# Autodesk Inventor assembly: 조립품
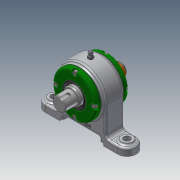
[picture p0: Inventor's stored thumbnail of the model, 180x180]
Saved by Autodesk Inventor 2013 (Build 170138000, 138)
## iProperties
Created: 2019-05
Part Number: 조립품
Document SubType Name: Assembly
Designer: user
Author: user
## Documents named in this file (14)
- C:\Users\user\Desktop\490504V1023\조립품.iam
- C:\Users\user\Desktop\490504V1023\본체.ipt
- C:\Users\user\Desktop\490504V1023\개스킷.ipt
- C:\Users\user\Desktop\490504V1023\그리스니플 M6.ipt
- 그리스니플  M6.ipt
- C:\Users\user\Desktop\490504V1023\그리스니플개스킷.ipt
- C:\Users\user\Desktop\490504V1023\볼트 M4.ipt
- C:\Users\user\Desktop\490504V1023\앵귤러 볼 베어링 7205.ipt
- C:\Users\user\Desktop\490504V1023\오일 실 28 40 5 B.ipt
- C:\Users\user\Desktop\490504V1023\커버.ipt
- C:\Users\user\Desktop\490504V1023\베어링너트_MIR.ipt
- C:\Users\user\Desktop\490504V1023\축_MIR.ipt
- C:\Users\user\Desktop\490504V1023\칼라_MIR.ipt
- C:\Users\user\Desktop\490504V1023\커버_MIR.ipt
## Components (4 placed, 3 different names)
1. 개스킷:1
2. 그리스니플  M6:1
3. 그리스니플개스킷:1
4. 개스킷:2
